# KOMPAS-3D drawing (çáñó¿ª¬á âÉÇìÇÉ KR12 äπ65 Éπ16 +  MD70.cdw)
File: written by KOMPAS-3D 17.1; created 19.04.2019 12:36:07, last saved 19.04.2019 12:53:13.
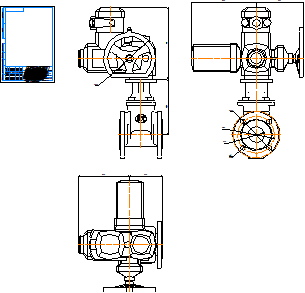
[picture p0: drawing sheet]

Sheet 1: A4, portrait

Title block, sheet 1: name: Задвижка ГРАНАР KR12 Ду65 Ру16 + / MD70; material: Внимание! Данный продукт является объектом авторского права ООО «Торговый Дом АДЛ». / Запрещается изменение, копирование, распространение / (в том числе путем копирования на другие сайты и ресурсы в Интернете) / или любое иное использование информации и объектов без предварительного / согласия правообладателя (ООО «Торговый Дом АДЛ»).; mass: 83,9; sheets: 1; organisation: ООО "Торговый дом АДЛ"; sheet format: A4; stored path: \\adlc.lan\data\АДЛ_ПКД\3D-модели\ADL production\Клиновые задвижки серии KR ГРАНАР\Клиновые задвижки KR12 с эл.приводами Смартгир\KOMPAS 2D\Задвижка ГРАНАР KR12 Ду65 Ру16 +  MD70.cdw

Views: Вид 1, Проекционный вид 2, Проекционный вид 3
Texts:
  user
Dimensions and other numbers on the sheet: 218; 282; 205; 253; 187; 185; 145; 65; 19; 4 Отв.; 200; 130; 1:1; 1; 83,9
